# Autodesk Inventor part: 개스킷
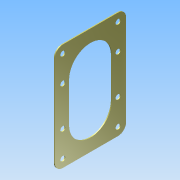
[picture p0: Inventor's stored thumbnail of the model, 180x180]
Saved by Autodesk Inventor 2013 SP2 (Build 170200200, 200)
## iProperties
Created: 2026-10
Part Number: 개스킷
Material: Generic
Document SubType Name: Modeling
Designer: a
Density: 1 g/cm^3
Author: a
변환 표준: STEP AP214IS
전처리기: Build: 200, Release: 2013 SP2 Update 6 - Date: Thu 07/17/2014
전송 단위: 밀리미터
불확실성: 0.01
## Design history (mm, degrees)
node "개스킷1"
node "솔리드1"
node "기준1"
